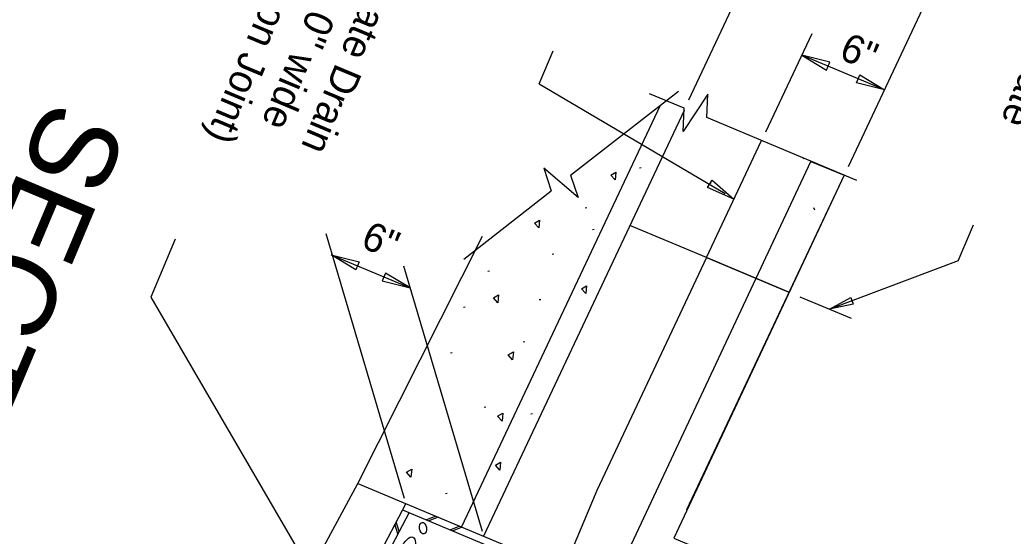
# Model space of a CAD drawing. Extents: x 1968564 to 1968711, y 796599 to 796794.
# Drawn here: x 1968598.8 to 1968616.17, y 796701.88 to 796710.91 of the extents above; entities that cross this region are included whole.
import ezdxf

# ---------------------------------------------------------------- set-up
doc = ezdxf.new("R2010")
doc.units = 0
for name, color, linetype in [('BR_AUTO DIMENSION', 7, 'Continuous'), ('BR_CONCRETE', 7, 'Continuous'), ('BR_DETAILS', 7, 'Continuous'), ('BR_GROUND LINES', 7, 'Continuous'), ('BR_STRUCTURAL STEEL', 7, 'Continuous'), ('BR_TABLE LINES', 7, 'Continuous'), ('BR_TEXT', 7, 'Continuous')]:
    doc.layers.add(name, color=color, linetype=linetype)

msp = doc.modelspace()

# ---------------------------------------------------------------- linework, layer by layer
at = {"layer": 'BR_AUTO DIMENSION'}
for p, q in [((1968612.153, 796713.03), (1968610.495, 796709.507)), ((1968614.946, 796711.87), (1968613.286, 796708.341)), ((1968612.652, 796710.666), (1968611.842, 796708.946)), ((1968607.884, 796709.79), (1968608.128, 796710.371)), ((1968613.922, 796709.687), (1968612.479, 796710.293)), ((1968607.884, 796709.79), (1968611.138, 796707.87)), ((1968615.212, 796706.692), (1968615.478, 796707.326)), ((1968604.152, 796707.173), (1968605.521, 796702.539)), ((1968601.522, 796707.071), (1968601.096, 796706.057)), ((1968604.246, 796706.797), (1968605.628, 796706.218)), ((1968615.212, 796706.692), (1968612.967, 796705.85)), ((1968605.512, 796706.608), (1968606.886, 796701.96)), ((1968601.096, 796706.057), (1968604.869, 796699.568))]:
    msp.add_line(p, q, dxfattribs=at)
for points in [[(1968612.969, 796710.169), (1968612.479, 796710.293), (1968612.911, 796710.03)], [(1968613.49, 796709.95), (1968613.922, 796709.687), (1968613.432, 796709.811)], [(1968610.907, 796708.104), (1968611.29, 796707.774), (1968610.827, 796707.977)], [(1968604.678, 796706.535), (1968604.246, 796706.797), (1968604.736, 796706.673)], [(1968605.138, 796706.342), (1968605.628, 796706.218), (1968605.196, 796706.48)], [(1968613.375, 796705.935), (1968612.959, 796705.847), (1968613.331, 796706.054)]]:
    msp.add_lwpolyline(points, close=True, dxfattribs=at)
msp.add_lwpolyline([(1968612.443, 796706.064), (1968613.338, 796705.689), (1968613.338, 796705.689)], dxfattribs=at)
at = {"layer": 'BR_CONCRETE'}
for p, q in [((1968609.998, 796709.411), (1968606.528, 796702.038)), ((1968610.417, 796709.325), (1968606.912, 796701.877)), ((1968613.216, 796708.193), (1968610.46, 796702.337)), ((1968610.808, 796706.75), (1968609.469, 796707.311)), ((1968609.469, 796707.311), (1968609.469, 796707.311)), ((1968610.808, 796706.75), (1968608.89, 796702.674)), ((1968610.808, 796706.75), (1968612.252, 796706.144)), ((1968604.715, 796702.799), (1968610.027, 796700.571)), ((1968608.89, 796702.674), (1968608.31, 796701.291))]:
    msp.add_line(p, q, dxfattribs=at)
at = {"layer": 'BR_DETAILS'}
for p, q in [((1968608.435, 796708.192), (1968610.323, 796709.665)), ((1968610.418, 796709.367), (1968609.814, 796709.614)), ((1968613.436, 796708.101), (1968610.818, 796709.199)), ((1968609.639, 796708.322), (1968609.669, 796708.328)), ((1968610.863, 796708.054), (1968610.892, 796708.06)), ((1968606.567, 796706.72), (1968608.097, 796707.921)), ((1968608.691, 796707.623), (1968608.72, 796707.629)), ((1968608.815, 796707.241), (1968608.844, 796707.246)), ((1968604.715, 796702.799), (1968606.891, 796707.125)), ((1968608.113, 796706.811), (1968608.142, 796706.817)), ((1968606.989, 796706.515), (1968607.018, 796706.52)), ((1968607.883, 796706.014), (1968607.912, 796706.019)), ((1968606.563, 796705.881), (1968606.593, 796705.887)), ((1968607.603, 796705.276), (1968607.633, 796705.282)), ((1968606.333, 796705.084), (1968606.363, 796705.089)), ((1968606.921, 796704.135), (1968606.95, 796704.141)), ((1968607.736, 796704.017), (1968607.766, 796704.023)), ((1968603.618, 796700.763), (1968604.715, 796702.799)), ((1968606.247, 796702.621), (1968606.277, 796702.626))]:
    msp.add_line(p, q, dxfattribs=at)
for points in [[(1968610.818, 796709.199), (1968610.834, 796709.611), (1968610.402, 796708.955), (1968610.418, 796709.367)], [(1968608.435, 796708.192), (1968608.564, 796707.801), (1968607.968, 796708.312), (1968608.097, 796707.921)], [(1968609.211, 796708.108), (1968609.135, 796708.195), (1968609.225, 796708.247), (1968609.211, 796708.108)], [(1968607.879, 796707.268), (1968607.803, 796707.354), (1968607.893, 796707.406), (1968607.879, 796707.268)], [(1968607.163, 796705.959), (1968607.087, 796706.046), (1968607.176, 796706.098), (1968607.163, 796705.959)], [(1968608.701, 796706.119), (1968608.624, 796706.205), (1968608.714, 796706.258), (1968608.701, 796706.119)], [(1968607.419, 796704.96), (1968607.343, 796705.046), (1968607.433, 796705.099), (1968607.419, 796704.96)], [(1968607.235, 796703.89), (1968607.158, 796703.976), (1968607.248, 796704.029), (1968607.235, 796703.89)], [(1968607.198, 796703.031), (1968607.121, 796703.117), (1968607.211, 796703.17), (1968607.198, 796703.031)], [(1968605.642, 796702.906), (1968605.566, 796702.992), (1968605.655, 796703.045), (1968605.642, 796702.906)]]:
    msp.add_lwpolyline(points, dxfattribs=at)
at = {"layer": 'BR_GROUND LINES'}
for centre, major_axis, ratio in [((1968605.854, 796702.015), (-0.015, 0.101), 0.604846), ((1968605.577, 796701.621), (0.099, 0.236), 0.439024)]:
    msp.add_ellipse(centre, major_axis=major_axis, ratio=ratio, dxfattribs=at)
at = {"layer": 'BR_STRUCTURAL STEEL'}
for p, q in [((1968612.514, 796708.472), (1968612.506, 796708.491)), ((1968612.704, 796707.58), (1968612.688, 796707.618)), ((1968612.704, 796707.58), (1968612.697, 796707.597)), ((1968605.553, 796702.448), (1968603.408, 796698.373)), ((1968605.61, 796702.288), (1968603.524, 796698.324)), ((1968605.494, 796702.336), (1968610.056, 796700.423)), ((1968605.434, 796701.954), (1968605.382, 796702.123)), ((1968606.077, 796702.227), (1968605.914, 796702.161)), ((1968606.118, 796702.21), (1968605.954, 796702.143)), ((1968605.413, 796701.915), (1968605.361, 796702.083)), ((1968606.496, 796702.052), (1968606.333, 796701.985)), ((1968606.537, 796702.035), (1968606.373, 796701.968))]:
    msp.add_line(p, q, dxfattribs=at)
msp.add_lwpolyline([(1968612.252, 796706.144), (1968610.808, 796706.75), (1968611.773, 796708.799)], dxfattribs=at)
at = {"layer": 'BR_TABLE LINES'}
msp.add_lwpolyline([(1968612.637, 796708.43), (1968613.216, 796708.193), (1968610.238, 796701.84), (1968611.606, 796701.264), (1968611.123, 796700.111), (1968609.155, 796700.937), (1968609.388, 796701.491), (1968610.779, 796700.907), (1968610.8, 796700.958), (1968609.411, 796701.549)], close=True, dxfattribs=at)

# ---------------------------------------------------------------- texts
at = {"layer": 'BR_AUTO DIMENSION'}
for height, p in [(0.5, (1968613.106, 796710.24)), (0.4999, (1968604.743, 796706.941))]:
    msp.add_text('6"', height=height, rotation=337.246, dxfattribs=at).set_placement(p)
at = {"layer": 'BR_TEXT'}
for s, height, p in [('End of Armor Plate', 0.49995, (1968618.134, 796714.364)), ('centered on Joint)', 0.49995, (1968604.124, 796713.806)), ('Field (1\'-0" wide', 0.49995, (1968604.862, 796713.496)), ('Aggregate Drain', 0.49995, (1968605.599, 796713.187)), ('SECTION H-H', 1.5, (1968599.319, 796709.564))]:
    msp.add_text(s, height=height, rotation=247.246, dxfattribs=at).set_placement(p)

doc.saveas('drawing.dxf')
